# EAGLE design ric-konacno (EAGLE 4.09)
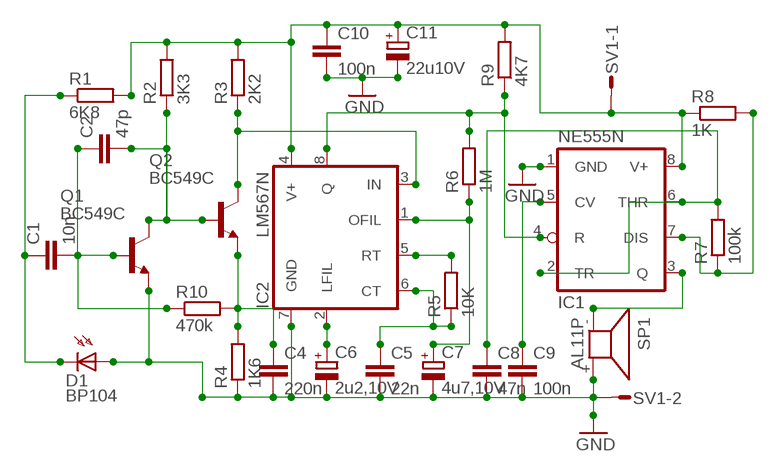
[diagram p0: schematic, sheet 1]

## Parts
C1  10n  C-EU050-030X075  [C050-030X075]
C2  47p  C-EU050-030X075  [C050-030X075]
C4  220n  C-EU050-030X075  [C050-030X075]
C5  22n  C-EU050-030X075  [C050-030X075]
C6  2u2,10V  CPOL-EUE3.5-8  [E3,5-8]
C7  4u7,10V  CPOL-EUE3.5-8  [E3,5-8]
C8  47n  C-EU050-030X075  [C050-030X075]
C9  100n  C-EU050-030X075  [C050-030X075]
C10  100n  C-EU050-030X075  [C050-030X075]
C11  22u10V  CPOL-EUE3.5-8  [E3,5-8]
D1  BP104  [BP104]
IC1  NE555N  [DIL08]
IC2  LM567N  [DIL08]
Q1  BC549C  [TO92-EBC]
Q2  BC549C  [TO92-EBC]
R1  6K8  R-EU_0207/10  [0207/10]
R2  3K3  R-EU_0207/10  [0207/10]
R3  2K2  R-EU_0207/10  [0207/10]
R4  1K6  R-EU_0207/10  [0207/10]
R5  10K  R-EU_0207/10  [0207/10]
R6  1M  R-EU_0207/10  [0207/10]
R7  100k  R-EU_0207/10  [0207/10]
R8  1K  R-EU_0207/10  [0207/10]
R9  4K7  R-EU_0207/10  [0207/10]
R10  470k  R-EU_0207/10  [0207/10]
SP1  AL11P  [AL11P]
SV1  L02P  [L02P]

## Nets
GND: C4.2 C5.2 C6.- C7.- C8.2 C9.2 D1.A IC1.1(GND) IC2.7(GND) Q1.E R4.1 SP1.+ SV1.2
N$1: C1.1 D1.K(C) R1.1
N$2: C1.2 C2.1 Q1.B R10.1
N$3: C6.+ IC2.2(LFIL)
N$4: C2.2 Q1.C Q2.B R2.1
N$5: C4.1 Q2.E R4.2 R10.2
N$6: C10.2 C11.- ; supply symbol labelled GND
N$7: C5.1 IC2.6(CT) R5.1
N$9: C8.1 IC1.2(TR) IC1.6(THR) R7.2
N$10: IC2.5(RT) R5.2
N$11: C9.1 IC1.5(CV)
N$12: C7.+ IC2.1(OFIL) R6.1
N$14: IC1.7(DIS) R7.1 R8.2
N$15: C10.1 C11.+ IC1.8(V+) IC2.4(V+) R1.2 R2.2 R3.2 R8.1 R9.2 SV1.1
N$16: IC1.4(R) IC2.8(Q) R6.2 R9.1
N$20: IC2.3(IN) Q2.C R3.1
N$22: IC1.3(Q) SP1.-

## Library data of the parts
C1 C2 C4 C5 C8-C10 = rcl:C-EU: CAPACITOR, European symbol
C6 C7 C11 = rcl:CPOL-EU: POLARIZED CAPACITOR, European symbol
D1 = opto-trans-siemens:BP104: PHOTO DIODE
IC1 = linear:*555: TIMER
IC2 = linear:*567: TONE DECODER
Q1 Q2 = transistor-npn:BC549*: NPN Transistor
R1-R10 = rcl:R-EU_: RESISTOR, European symbol
SP1 = buzzer:AL11P: SPEAKER
SV1 = con-amp-mt:L02P: AMP MT CONNECTOR

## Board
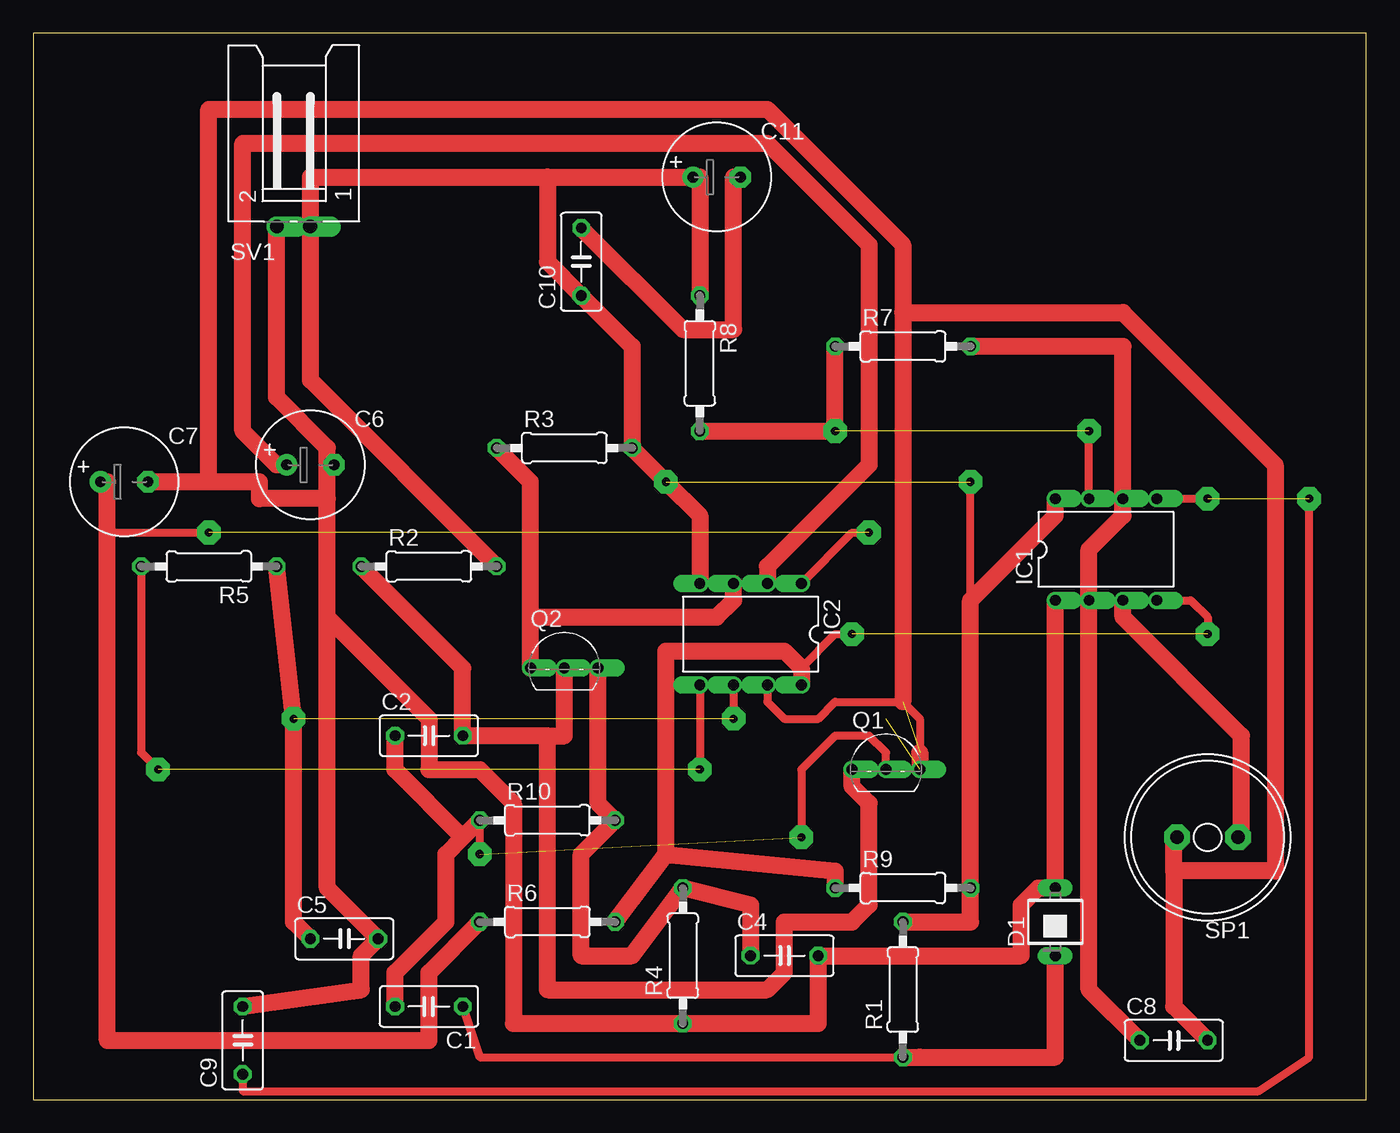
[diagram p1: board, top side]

Size 100 x 80 mm. Coordinates in mm from the lower left corner, seen from the top.
Outline: 0,0 100,0 100,80 0,80 0,0
Copper layers used: Top

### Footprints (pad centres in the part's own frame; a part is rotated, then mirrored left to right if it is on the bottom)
C050-030X075 = drill 0.813 octagon: 1 -2.54,0; 2 2.54,0
E3,5-8 = drill 0.813 pad 1.6 round: + -1.778,0 | drill 0.813 pad 1.6 octagon: - 1.778,0
BP104 = drill 0.813 long: A 0,2.54; K 0,-2.54
DIL08 = drill 0.813 offset: 1 -3.81,-3.81; 2 -1.27,-3.81; 3 1.27,-3.81; 4 3.81,-3.81; 5 3.81,3.81; 6 1.27,3.81; 7 -1.27,3.81; 8 -3.81,3.81
TO92-EBC = drill 0.813 offset: B 0,-1.27; C -2.54,-1.27; E 2.54,-1.27
0207/10 = drill 0.813 octagon: 1 -5.08,0; 2 5.08,0
AL11P = drill 1.016 pad 1.905 octagon: + 2.286,0; - -2.286,0
L02P = drill 1.016 offset: 1 1.25,-6.25; 2 -1.25,-6.25

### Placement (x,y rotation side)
C1  29.68,6.98 180 top
C2  29.68,27.3 0 top
C4  56.35,10.79 0 top
C5  23.33,12.06 0 top
C6  20.79,47.62 0 top
C7  6.82,46.35 0 top
C8  85.56,4.44 0 top
C9  15.71,4.44 90 top
C10  41.11,62.86 90 top
C11  51.27,69.21 0 top
D1  76.67,13.33 0 top
IC1  80.48,41.27 0 top
IC2  53.81,34.92 180 top
Q1  63.97,26.03 0 top
Q2  39.84,33.65 0 top
R1  65.24,8.25 90 top
R2  29.68,40 0 top
R3  39.84,48.89 0 top
R4  48.73,10.79 90 top
R5  13.17,40 180 top
R6  38.57,13.33 0 top
R7  65.24,56.51 0 top
R8  50,55.24 270 top
R9  65.24,15.87 0 top
R10  38.57,20.95 0 top
SP1  88.1,19.68 180 top
SV1  19.52,71.75 0 top

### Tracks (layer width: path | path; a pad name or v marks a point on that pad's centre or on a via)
1A  (via drill 0.61 pad 1.78)
  other vias: 9.36,24.76
GND  (2 unrouted)
  Top 0.61: IC2.7 55.08,29.84 56.35,28.57 58.89,28.57 60.16,29.84 65.24,29.84 66.51,28.57 66.51,26.03
  Top 1.27: IC1.1 D1.A 75.4,15.87 74.13,14.6 74.13,10.79 C4.2 58.89,5.71 R4.1 36.03,5.71 36.03,22.22 33.49,24.76 29.68,24.76 29.68,28.57 22.06,36.19 | C8.2 85.56,6.98 85.56,17.14 | 85.56,17.14 85.56,19.68 SP1.+ | 66.51,26.03 Q1.E | C9.2 24.6,8.25 24.6,10.79 C5.2 22.06,15.87 22.06,36.19 | 22.06,47.62 22.06,48.89 18.25,52.7 18.25,64.13 SV1.2 | 13.17,46.35 16.98,46.35 16.98,45.08 22.06,45.08 | 22.06,45.08 22.06,47.62 | 13.17,46.35 C7.- | 22.06,47.62 C6.- | 22.06,36.19 22.06,45.08 | 65.24,59.05 65.24,64.13 55.08,74.29 13.17,74.29 13.17,46.35 | 65.24,59.05 65.24,29.84 | 85.56,17.14 93.18,17.14 93.18,47.62 81.75,59.05 65.24,59.05
N$1
  Top 0.61: C1.1 33.49,3.17 66.51,3.17
  Top 1.27: R1.1 66.51,3.17 76.67,3.17 D1.K
N$2  (via drill 0.61 pad 1.78)  (1 unrouted)
  Top 0.61: Q1.B 63.97,26.03 62.7,27.3 60.16,27.3 57.62,24.76 v57.62,19.68 | R10.1 v33.49,18.41
  Top 1.27: C1.2 27.14,9.52 30.95,13.33 30.95,18.41 32.22,19.68 | 32.22,19.68 R10.1 | C2.1 27.14,24.76 32.22,19.68
N$3
  Top 1.27: IC2.2 55.08,40 62.7,47.62 62.7,64.13 55.08,71.75 15.71,71.75 15.71,50.16 18.25,47.62 C6.+
N$4
  Top 1.27: 38.57,27.3 39.84,27.3 Q2.B | 38.57,27.3 C2.2 32.22,32.38 R2.1 | 38.57,27.3 38.57,8.25 55.08,8.25 56.35,9.52 56.35,13.33 61.43,13.33 62.7,14.6 62.7,22.22 61.43,23.49 Q1.C
N$5
  Top 1.27: C4.1 53.81,14.6 R4.2 44.92,10.79 41.11,10.79 41.11,18.41 R10.2 42.38,22.22 Q2.E
N$6
  Top 1.27: C10.2 48.73,57.78 52.54,57.78 52.54,69.21 C11.-
N$7  (via drill 0.61 pad 1.78)  (1 unrouted)
  Top 0.61: IC2.6 v52.54,28.57
  Top 1.27: R5.1 v19.52,28.57 19.52,13.33 C5.1
N$8  (via drill 0.61 pad 1.78)
  other vias: 79.21,50.16
N$9
  Top 1.27: C8.1 79.21,8.25 IC1.2 79.21,41.27 81.75,43.81 IC1.6 81.75,56.51 R7.2
N$10  (via drill 0.61 pad 1.78)  (1 unrouted)
  Top 0.61: R5.2 8.09,26.03 9.36,24.76 | IC2.5 v50,24.76
N$11  (via drill 0.61 pad 1.78)  (1 unrouted)
  Top 0.61: C9.1 15.71,0.63 91.91,0.63 95.72,3.17 v95.72,45.08 | IC1.5 88.1,45.08
N$12  (via drill 0.61 pad 1.78)  (1 unrouted)
  Top 0.61: 5.55,42.54 v13.17,42.54 | IC2.1 61.43,42.54 v62.7,42.54
  Top 1.27: R6.1 29.68,9.52 29.68,4.44 5.55,4.44 5.55,42.54 5.55,46.35 C7.+
N$14  (via drill 0.61 pad 1.78)  (1 unrouted)
  Top 0.61: IC1.7 79.21,50.16
  Top 1.27: R8.2 v60.16,50.16 R7.1
N$15  (via drill 0.61 pad 1.78)  (1 unrouted)
  Top 0.61: 70.32,37.46 v70.32,46.35
  Top 1.27: R1.2 70.32,13.33 R9.2 70.32,37.46 76.67,43.81 IC1.8 | IC2.4 50,43.81 v47.46,46.35 R3.2 44.92,56.51 C10.1 38.57,62.86 38.57,69.21 | R8.1 50,69.21 C11.+ 38.57,69.21 | R2.2 20.79,53.97 20.79,64.13 SV1.1 20.79,66.67 20.79,69.21 38.57,69.21
N$16  (via drill 0.61 pad 1.78)  (1 unrouted)
  Top 0.61: 57.62,32.38 60.16,34.92 v61.43,34.92 | IC1.4 86.83,37.46 88.1,36.19 v88.1,34.92
  Top 1.27: R6.2 47.46,18.41 | 47.46,18.41 60.16,17.14 R9.1 | 47.46,18.41 47.46,33.65 56.35,33.65 57.62,32.38 IC2.8
N$17  (via drill 0.61 pad 1.78)
  other vias: 88.1,45.08
N$20
  Top 1.27: R3.1 37.3,46.35 37.3,36.19 | Q2.C 37.3,36.19 | 37.3,36.19 51.27,36.19 52.54,37.46 IC2.3
N$22
  Top 1.27: IC1.3 81.75,36.19 90.64,27.3 90.64,19.68 SP1.-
